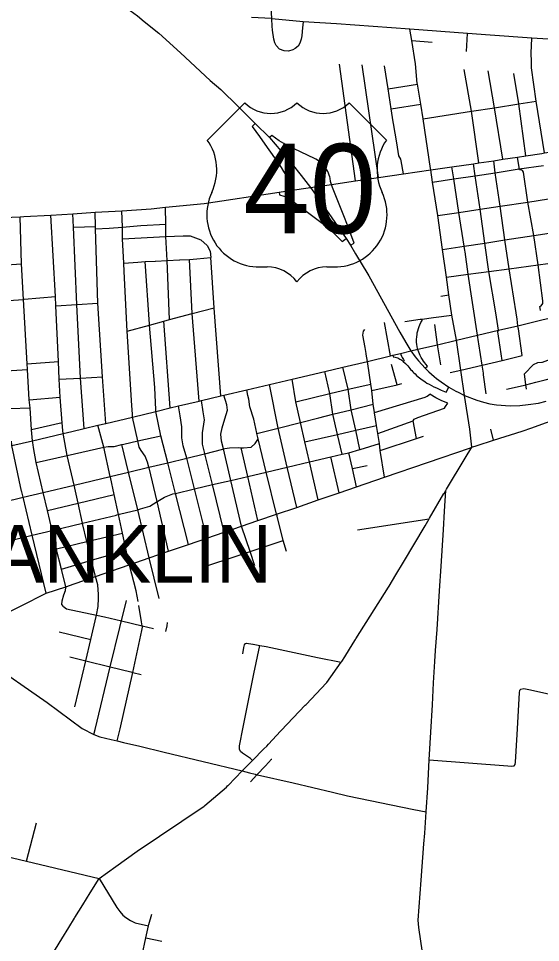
# Model space of a CAD drawing. Extents: x 1755200 to 1902939, y 644115 to 788070.
# Drawn here: x 1811230 to 1819343, y 701476 to 715838 of the extents above; entities that cross this region are included whole.
import ezdxf

# ---------------------------------------------------------------- set-up
doc = ezdxf.new("R2010")
doc.units = 0
for name, color, linetype in [('GM_X_City_Street', 7, 'Continuous'), ('GM_X_County_Road', 7, 'Continuous'), ('GM_X_Interchange_Ramps', 7, 'Continuous'), ('GM_X_Interstate_Route', 7, 'Continuous'), ('GM_X_Township_Road', 7, 'Continuous'), ('GM_X_Township_Text', 7, 'Continuous'), ('GM_X_US_Route', 7, 'Continuous'), ('GM_X_US_Shield', 7, 'Continuous')]:
    doc.layers.add(name, color=color, linetype=linetype)

msp = doc.modelspace()

# ---------------------------------------------------------------- linework, layer by layer
at = {"layer": 'GM_X_City_Street'}
for points in [[(1815173, 715717), (1815167, 715834), (1815156, 716028), (1815156, 716120), (1815160, 716213), (1815173, 716390), (1815193, 716667), (1815266, 717013)], [(1815164, 715835), (1814849, 715853)], [(1817314, 715673), (1816174, 715756), (1815653, 715786), (1815167, 715834), (1815164, 715835)], [(1815632, 715569), (1815621, 715518), (1815602, 715455), (1815574, 715407), (1815531, 715370), (1815495, 715351), (1815424, 715332), (1815357, 715336), (1815288, 715363), (1815236, 715416), (1815215, 715459), (1815198, 715518), (1815177, 715654), (1815173, 715717)], [(1815653, 715786), (1815643, 715691), (1815633, 715574), (1815632, 715569)], [(1819634, 715506), (1819210, 715534), (1818559, 715578), (1818207, 715605), (1817314, 715673)], [(1817633, 713505), (1817517, 714278), (1817480, 714507), (1817430, 714816), (1817428, 714828), (1817400, 715133), (1817342, 715495), (1817314, 715673)], [(1818194, 715322), (1818207, 715605)], [(1819201, 715171), (1819198, 715300), (1819210, 715534)], [(1817342, 715495), (1817659, 715470)], [(1816466, 713313), (1816217, 715127)], [(1816823, 713365), (1816573, 715119)], [(1817054, 714231), (1817022, 714433), (1816973, 714743), (1816916, 715100)], [(1819403, 713749), (1819276, 714553), (1819204, 715069), (1819201, 715171)], [(1818382, 713593), (1818269, 714396), (1818157, 715046)], [(1818756, 713649), (1818628, 714451), (1818530, 715024)], [(1819116, 713703), (1819003, 714510), (1818926, 714985)], [(1816973, 714743), (1817430, 714816)], [(1817517, 714278), (1818269, 714396), (1818628, 714451), (1819003, 714510), (1819276, 714553)], [(1817022, 714433), (1817480, 714507)], [(1817175, 713626), (1817170, 713652), (1817139, 713701), (1817108, 713905), (1817058, 714207), (1817054, 714231)], [(1819009, 713521), (1818984, 713684)], [(1817211, 713422), (1817176, 713623), (1817175, 713626)], [(1818169, 712211), (1818166, 712232), (1818156, 712299), (1818072, 712824), (1817995, 713343), (1817965, 713531)], [(1817995, 713343), (1818327, 713393), (1818640, 713441), (1819012, 713500), (1819390, 713554)], [(1818748, 710520), (1818701, 710832), (1818679, 710967), (1818688, 710994), (1818646, 711261), (1818537, 711906), (1818478, 712348), (1818404, 712874), (1818327, 713393), (1818303, 713580)], [(1818978, 711164), (1818964, 711261), (1818854, 711948), (1818788, 712395), (1818717, 712921), (1818640, 713441), (1818617, 713626)], [(1819343, 711297), (1819342, 711302), (1819333, 711362), (1819353, 711372), (1819376, 711409), (1819376, 711450), (1819304, 712008), (1819237, 712464), (1819143, 712985), (1819076, 713449), (1819063, 713477), (1819041, 713487), (1819014, 713487), (1819012, 713500), (1819009, 713521)], [(1817819, 712248), (1817745, 712775), (1817666, 713295), (1817636, 713485), (1817633, 713505)], [(1817666, 713295), (1817995, 713343)], [(1817745, 712775), (1818072, 712824), (1818404, 712874), (1818717, 712921), (1819143, 712985), (1819468, 713033), (1819623, 713055)], [(1812253, 709466), (1812195, 710249), (1812139, 711391), (1812086, 712592), (1812076, 712803)], [(1812589, 709545), (1812534, 710266), (1812465, 711412), (1812427, 712570), (1812425, 712607), (1812422, 712827)], [(1813001, 709686), (1812990, 709821), (1812919, 710977), (1812872, 711906), (1812865, 712034), (1812846, 712414), (1812846, 712596), (1812835, 712849)], [(1813578, 711158), (1813538, 712077), (1813522, 712447), (1813522, 712643), (1813516, 712905)], [(1811465, 709169), (1811457, 709212), (1811446, 709272), (1811432, 709443), (1811413, 709787), (1811395, 709908), (1811369, 710384), (1811369, 710388), (1811364, 710470), (1811309, 711472), (1811279, 712024), (1811256, 712755)], [(1811918, 709434), (1811908, 709555), (1811878, 709951), (1811862, 710233), (1811850, 710504), (1811812, 711369), (1811805, 711515), (1811735, 712781)], [(1812086, 712592), (1812425, 712607)], [(1812427, 712570), (1812641, 712579), (1812846, 712596)], [(1812846, 712596), (1813132, 712618), (1813522, 712643)], [(1812846, 712414), (1813522, 712447), (1813788, 712459), (1813867, 712457)], [(1813867, 712457), (1813869, 712457), (1813896, 712457), (1814061, 712399), (1814161, 712310), (1814209, 712220), (1814219, 712122)], [(1813358, 712068), (1813538, 712077), (1813733, 712087), (1813735, 712087)], [(1813735, 712087), (1813885, 712094), (1814004, 712104), (1814004, 712104)], [(1814038, 709890), (1813929, 711251), (1813885, 712094)], [(1814004, 712104), (1814219, 712122)], [(1814270, 711335), (1814269, 711340), (1814219, 712122)], [(1818383, 710781), (1818378, 710811), (1818361, 710916), (1818220, 711864), (1818169, 712211)], [(1810647, 711977), (1810973, 712002), (1811279, 712024)], [(1812865, 712034), (1813082, 712052), (1813086, 712052)], [(1813086, 712052), (1813196, 712061), (1813354, 712068), (1813358, 712068)], [(1813267, 711087), (1813196, 712061)], [(1817879, 711819), (1818220, 711864), (1818537, 711906), (1818854, 711948), (1819304, 712008), (1819608, 712048), (1819763, 712068)], [(1810682, 711426), (1810995, 711449), (1811309, 711472), (1811317, 711473), (1811805, 711515)], [(1817794, 711523), (1817917, 711542)], [(1811812, 711369), (1812139, 711391), (1812465, 711412)], [(1812919, 710977), (1813268, 711071), (1813491, 711131), (1813578, 711158), (1813929, 711251), (1814269, 711340)], [(1814374, 709971), (1814270, 711334), (1814270, 711335)], [(1817235, 711129), (1817470, 711162), (1817504, 711166), (1817680, 711191), (1817962, 711224)], [(1818037, 710839), (1818361, 710916), (1818688, 710994), (1818992, 711063), (1819364, 711153), (1819710, 711233), (1819868, 711271), (1820152, 711337)], [(1813364, 709756), (1813347, 710101), (1813268, 711071), (1813268, 711073), (1813267, 711084), (1813267, 711087)], [(1813588, 709784), (1813491, 711131)], [(1817010, 710596), (1816918, 711113)], [(1817739, 710767), (1817698, 711081)], [(1819000, 711012), (1818997, 711028), (1818992, 711063), (1818978, 711164)], [(1816632, 710631), (1816618, 710722), (1816581, 710916), (1816590, 710976), (1816614, 711006)], [(1819056, 710601), (1819000, 711012)], [(1811127, 709200), (1811446, 709272), (1811922, 709387), (1812059, 709420), (1812253, 709466), (1812465, 709515), (1812589, 709545), (1813004, 709643), (1813365, 709730), (1813588, 709784), (1813719, 709816), (1814038, 709890), (1814074, 709898), (1814374, 709971), (1814422, 709982), (1814779, 710066), (1815131, 710149), (1815483, 710232), (1815989, 710351), (1816269, 710420), (1816652, 710508), (1817010, 710596), (1817048, 710605), (1817167, 710633), (1817329, 710673), (1817435, 710700), (1817739, 710767), (1818037, 710839)], [(1818458, 710301), (1818455, 710326), (1818437, 710451), (1818383, 710781)], [(1817791, 710454), (1817739, 710767)], [(1819270, 710185), (1819415, 710223), (1819688, 710296), (1819991, 710376), (1819999, 710377), (1820295, 710439), (1820612, 710506), (1820953, 710578), (1821276, 710647), (1821610, 710723), (1821757, 710761)], [(1811364, 710470), (1811850, 710504)], [(1816918, 708708), (1816852, 709123), (1816838, 709233), (1816813, 709385), (1816793, 709511), (1816761, 709708), (1816761, 709712), (1816741, 709842), (1816721, 710055), (1816707, 710155), (1816686, 710292), (1816652, 710508), (1816634, 710620), (1816632, 710631)], [(1817937, 710337), (1818104, 710374), (1818437, 710451), (1818590, 710485), (1818748, 710520), (1819056, 710601)], [(1819092, 710317), (1819235, 710462), (1819301, 710490), (1819365, 710498), (1819371, 710498), (1819630, 710593), (1819641, 710596), (1819767, 710624)], [(1810389, 710321), (1810737, 710343), (1811039, 710362), (1811369, 710384)], [(1816262, 709064), (1816189, 709373), (1816115, 709686), (1816067, 710008), (1815989, 710351)], [(1816537, 709139), (1816471, 709437), (1816401, 709757), (1816352, 710074), (1816269, 710420)], [(1817116, 710146), (1817029, 710461)], [(1811862, 710233), (1812195, 710249), (1812534, 710266)], [(1815886, 708354), (1815750, 708945), (1815678, 709257), (1815610, 709558), (1815538, 709881), (1815483, 710232)], [(1818499, 710002), (1818458, 710301)], [(1819125, 710074), (1819116, 710143), (1819092, 710317)], [(1815249, 708103), (1815249, 708105), (1815242, 708133), (1815081, 708788), (1814956, 709303), (1814936, 709385), (1814934, 709392), (1814886, 709610), (1814824, 709804), (1814809, 709920), (1814795, 709979), (1814779, 710066)], [(1815553, 708239), (1815406, 708865), (1815263, 709469), (1815131, 710149)], [(1815538, 709881), (1816067, 710008), (1816352, 710074), (1816707, 710155)], [(1816721, 710055), (1817116, 710146), (1817185, 710162)], [(1818815, 710075), (1819074, 710133), (1819094, 710138), (1819116, 710143), (1819270, 710185)], [(1811395, 709908), (1811878, 709951)], [(1814700, 707931), (1814695, 707945), (1814529, 708658), (1814415, 709147), (1814386, 709267), (1814373, 709375), (1814393, 709477), (1814434, 709613), (1814476, 709748), (1814468, 709833), (1814422, 709982)], [(1816761, 709712), (1817552, 709950), (1817583, 709965), (1817625, 710000)], [(1817901, 709859), (1817808, 709896), (1817715, 709939), (1817625, 710000)], [(1810424, 709718), (1810770, 709745), (1811095, 709774), (1811413, 709787)], [(1814159, 707761), (1813965, 708526), (1813844, 709002), (1813789, 709197), (1813769, 709318), (1813768, 709493), (1813744, 709660), (1813719, 709816)], [(1814428, 707853), (1814245, 708592), (1814126, 709070), (1814125, 709077), (1814088, 709224), (1814088, 709298), (1814092, 709398), (1814110, 709530), (1814119, 709598), (1814111, 709663), (1814100, 709725), (1814074, 709898)], [(1814936, 709385), (1815263, 709469), (1815610, 709558), (1815897, 709631), (1816115, 709686), (1816401, 709757), (1816741, 709842)], [(1816813, 709385), (1817364, 709584), (1817380, 709609), (1817436, 709636), (1817850, 709782), (1817868, 709807), (1817901, 709859)], [(1813563, 707557), (1813383, 708329), (1813261, 708853), (1813258, 708863), (1813235, 708944), (1813197, 709033), (1813137, 709123), (1813104, 709176), (1813085, 709271), (1813084, 709275), (1813004, 709643), (1813001, 709686)], [(1813874, 707663), (1813672, 708457), (1813551, 708933), (1813444, 709353), (1813365, 709730), (1813364, 709756)], [(1811908, 709555), (1811432, 709443)], [(1812952, 707347), (1812904, 707572), (1812847, 707839), (1812784, 708128), (1812718, 708438), (1812659, 708709), (1812657, 708720), (1812554, 709175), (1812465, 709515)], [(1815678, 709257), (1816189, 709373), (1816471, 709437), (1816793, 709511)], [(1817415, 709308), (1817364, 709584)], [(1818360, 709201), (1818612, 709282), (1819059, 709426), (1819208, 709477), (1819422, 709552), (1819508, 709582), (1819562, 709600)], [(1811507, 708936), (1811987, 709046), (1812554, 709175), (1812625, 709186), (1812715, 709187), (1812837, 709215), (1812869, 709222), (1813085, 709271), (1813444, 709353)], [(1812422, 707187), (1812366, 707416), (1812294, 707707), (1812225, 707989), (1812224, 707993), (1812155, 708304), (1812093, 708585), (1811987, 709046), (1811931, 709362), (1811922, 709387), (1811918, 709434)], [(1816852, 709123), (1817415, 709308), (1817526, 709345)], [(1818612, 709282), (1818569, 709455)], [(1811277, 708492), (1811127, 709200), (1811123, 709267)], [(1813417, 706822), (1813263, 707454), (1813082, 708203), (1812940, 708787), (1812837, 709215)], [(1812952, 707347), (1813263, 707454), (1813563, 707557), (1813874, 707663), (1814159, 707761), (1814428, 707853), (1814695, 707945), (1814952, 708033), (1815242, 708133), (1815553, 708239), (1815886, 708354), (1816215, 708467), (1816485, 708559), (1816918, 708708), (1818255, 709167), (1818275, 709174), (1818360, 709201)], [(1814436, 709152), (1814437, 709152), (1814508, 709167), (1814648, 709168), (1814691, 709165), (1814728, 709162), (1814845, 709175), (1814910, 709230), (1814938, 709279), (1814956, 709303)], [(1816538, 709139), (1816838, 709233)], [(1809639, 708001), (1810005, 708088), (1810353, 708171), (1810659, 708244), (1810988, 708322), (1811300, 708397), (1811615, 708472), (1812093, 708585), (1812657, 708720), (1812940, 708787), (1813258, 708863), (1813551, 708933), (1813844, 709002), (1814122, 709069), (1814126, 709070), (1814407, 709146), (1814415, 709147), (1814436, 709152)], [(1811889, 707308), (1811886, 707319), (1811833, 707540), (1811820, 707593), (1811753, 707880), (1811681, 708191), (1811615, 708472), (1811507, 708936), (1811465, 709169)], [(1812752, 708120), (1812754, 708121), (1812784, 708128), (1812800, 708132), (1813082, 708203), (1813125, 708214), (1813272, 708259), (1813383, 708329), (1813397, 708338), (1813500, 708400), (1813630, 708447), (1813672, 708457), (1813965, 708526), (1814245, 708592), (1814455, 708641), (1814529, 708658), (1814793, 708721), (1815081, 708788), (1815406, 708865), (1815750, 708945), (1816086, 709025), (1816262, 709064), (1816365, 709088), (1816537, 709139), (1816538, 709139)], [(1814952, 708033), (1814793, 708721), (1814691, 709165)], [(1816485, 708559), (1816421, 708841), (1816365, 709088)], [(1816215, 708467), (1816086, 709025)], [(1816421, 708841), (1816647, 708890)], [(1811659, 706904), (1811442, 707805), (1811300, 708397), (1811280, 708480), (1811277, 708492)], [(1817851, 708181), (1817869, 708501)], [(1811681, 708191), (1812155, 708304), (1812718, 708438)], [(1810815, 707653), (1810815, 707653), (1811125, 707728), (1811442, 707805), (1811753, 707880), (1812224, 707993), (1812752, 708120)], [(1815395, 707553), (1815343, 707722), (1815249, 708103)], [(1814905, 707332), (1814830, 707552), (1814700, 707930), (1814700, 707931)], [(1811820, 707593), (1812294, 707707), (1812847, 707839)], [(1814611, 707480), (1814611, 707480), (1814830, 707552), (1815343, 707722)], [(1811896, 707279), (1812366, 707416), (1812904, 707572)], [(1814124, 707319), (1814611, 707480)], [(1807606, 707144), (1807927, 707100), (1807937, 707099), (1808229, 707057), (1808515, 707017), (1808525, 707015), (1808870, 706939), (1809249, 706853), (1809618, 706775), (1809997, 706692), (1810006, 706690), (1810372, 706605), (1810720, 706524), (1810820, 706507), (1810850, 706503), (1810880, 706511), (1811659, 706904), (1811963, 707006), (1812095, 707050), (1812428, 707165), (1812952, 707347)], [(1813092, 706774), (1813060, 706942), (1812954, 707342), (1812952, 707347)], [(1811930, 706699), (1811903, 706731), (1811907, 706787), (1811933, 706879), (1811959, 706945), (1811966, 706993), (1811963, 707006), (1811896, 707279), (1811889, 707308)], [(1812472, 706826), (1812472, 706831), (1812475, 706884), (1812462, 707033), (1812428, 707165), (1812422, 707187)], [(1812105, 705139), (1812275, 705853), (1812354, 706187), (1812438, 706542), (1812442, 706563), (1812466, 706699), (1812472, 706826)], [(1812805, 706370), (1812827, 706460), (1812830, 706474), (1812908, 706791)], [(1811930, 706699), (1811975, 706662), (1812442, 706563), (1812564, 706537), (1812830, 706474), (1813154, 706397), (1813328, 706356)], [(1812761, 704608), (1812811, 704798), (1813005, 705673), (1813149, 706323), (1813158, 706379), (1813154, 706397), (1813140, 706460), (1813098, 706715)], [(1812401, 704708), (1812420, 704788), (1812657, 705759), (1812805, 706370)], [(1813518, 706311), (1813541, 706398), (1813548, 706449)], [(1811863, 706305), (1812354, 706187)], [(1810583, 705964), (1810591, 705959), (1810735, 705861), (1811674, 705206), (1812217, 704801), (1812401, 704708), (1812492, 704675), (1812669, 704629), (1812761, 704608), (1812860, 704585)], [(1812026, 705915), (1812275, 705853), (1812657, 705759), (1812976, 705681)], [(1812976, 705681), (1812976, 705681), (1813005, 705673), (1813134, 705642)], [(1812860, 704585), (1813118, 704525), (1813496, 704435), (1814706, 704145)], [(1804587, 704387), (1804884, 704291), (1805626, 704054), (1806239, 703914), (1806558, 703842), (1806871, 703772), (1807204, 703697), (1807447, 703642), (1807701, 703584), (1807975, 703522), (1808509, 703402), (1809302, 703223), (1809996, 703066), (1810269, 703001), (1810590, 702923), (1811352, 702740), (1811574, 702687), (1812483, 702469)], [(1814834, 703972), (1814936, 704083), (1815066, 704222), (1815164, 704327), (1815165, 704328)], [(1814706, 704145), (1814820, 704114), (1814908, 704090)], [(1811352, 702740), (1811508, 703338)], [(1812483, 702469), (1812756, 702022), (1812804, 701958), (1812853, 701903), (1812896, 701866), (1812969, 701816), (1813044, 701781), (1813249, 701734)], [(1813255, 701754), (1813255, 701755), (1813300, 701915)], [(1813070, 700880), (1813154, 701278), (1813210, 701548), (1813249, 701734), (1813255, 701754)], [(1813210, 701548), (1813458, 701496)]]:
    msp.add_lwpolyline(points, dxfattribs=at)
at = {"layer": 'GM_X_County_Road'}
for points in [[(1817533, 701143), (1817450, 701707), (1817443, 701825), (1817489, 702443), (1817530, 703011), (1817543, 703177), (1817566, 703505), (1817591, 703881), (1817611, 704316), (1817637, 704743), (1817662, 705171), (1817682, 705514), (1817701, 705841), (1817711, 706013), (1817734, 706340), (1817775, 706942), (1817801, 707326), (1817835, 707892), (1817851, 708181)], [(1817611, 704316), (1818834, 704221), (1818895, 704215), (1818932, 704220), (1818946, 704242), (1818954, 704280), (1818979, 704707), (1819015, 705356), (1819023, 705398), (1819037, 705412), (1819083, 705422), (1819185, 705402), (1819948, 705233)]]:
    msp.add_lwpolyline(points, dxfattribs=at)
at = {"layer": 'GM_X_Interchange_Ramps'}
for points in [[(1814906, 714207), (1814863, 714158), (1814977, 714002), (1815095, 713835), (1815259, 713601), (1815313, 713520), (1815350, 713460), (1815369, 713429), (1815382, 713402), (1815394, 713372), (1815402, 713347), (1815409, 713321), (1815415, 713293), (1815419, 713256), (1815423, 713231), (1815435, 713201), (1815449, 713162)], [(1816095, 713258), (1816079, 713305), (1816071, 713356), (1816066, 713377), (1816058, 713405), (1816048, 713431), (1816036, 713457), (1816021, 713486), (1816005, 713512), (1815984, 713539), (1815964, 713562), (1815942, 713585), (1815914, 713609), (1815879, 713634), (1815851, 713650), (1815832, 713660), (1815513, 713811), (1815472, 713829), (1815429, 713850), (1815391, 713870), (1815352, 713893), (1815319, 713913), (1815281, 713938), (1815169, 714017), (1815133, 713987)], [(1816388, 712313), (1816444, 712346), (1816409, 712443), (1816383, 712510), (1816359, 712577), (1816342, 712626), (1816285, 712770), (1816112, 713213), (1816095, 713258)], [(1815281, 713137), (1815287, 713096), (1815356, 713076), (1815386, 713064), (1815412, 713052), (1815442, 713035), (1815468, 713016), (1815497, 712993), (1815868, 712716), (1815969, 712640), (1816055, 712572), (1816085, 712543), (1816108, 712521), (1816130, 712500), (1816156, 712475), (1816181, 712450), (1816203, 712428), (1816224, 712407), (1816258, 712372), (1816322, 712420)], [(1815449, 713162), (1815456, 713115), (1815462, 713092), (1815471, 713068), (1815482, 713047), (1815492, 713031), (1815510, 713010), (1815497, 712993)], [(1817551, 710401), (1817586, 710432), (1817561, 710464), (1817543, 710486), (1817524, 710511), (1817508, 710535), (1817488, 710569), (1817473, 710597), (1817460, 710626), (1817450, 710651), (1817441, 710678), (1817435, 710700), (1817433, 710706), (1817426, 710738), (1817421, 710773), (1817417, 710809), (1817416, 710848), (1817418, 710890), (1817423, 710928), (1817427, 710951), (1817434, 710984), (1817444, 711018), (1817455, 711051), (1817467, 711078), (1817483, 711110), (1817494, 711130), (1817501, 711142), (1817504, 711166)], [(1817048, 710605), (1817052, 710579), (1817086, 710573), (1817102, 710569), (1817123, 710561), (1817142, 710553), (1817156, 710545), (1817171, 710536), (1817186, 710525), (1817210, 710505), (1817244, 710477), (1817261, 710460), (1817272, 710448), (1817279, 710438), (1817295, 710418), (1817310, 710400), (1817324, 710384), (1817341, 710365), (1817356, 710348), (1817373, 710332), (1817392, 710313), (1817417, 710290), (1817439, 710270), (1817460, 710253), (1817480, 710237), (1817504, 710220), (1817527, 710204), (1817551, 710188), (1817578, 710171), (1817612, 710152), (1817647, 710133), (1817684, 710115), (1817726, 710097), (1817799, 710063), (1817877, 710031), (1817920, 710107)], [(1817167, 710633), (1817171, 710613), (1817182, 710590), (1817195, 710567), (1817204, 710551), (1817214, 710535), (1817226, 710515), (1817210, 710505)]]:
    msp.add_lwpolyline(points, dxfattribs=at)
at = {"layer": 'GM_X_Interstate_Route'}
for points in [[(1812533, 716247), (1812678, 716161), (1812775, 716100), (1812908, 716002), (1813077, 715880), (1813183, 715790), (1813411, 715611), (1813749, 715304), (1814209, 714873), (1814376, 714732), (1814645, 714472), (1814906, 714207), (1815133, 713987), (1815483, 713571), (1815623, 713399), (1815769, 713210)], [(1815769, 713210), (1815857, 713086)], [(1815857, 713086), (1815971, 712926), (1816322, 712420), (1816388, 712313), (1816469, 712178)], [(1816469, 712178), (1816660, 711864)], [(1816660, 711864), (1816675, 711839), (1817158, 710962), (1817251, 710800), (1817329, 710673)], [(1817329, 710673), (1817397, 710581), (1817448, 710516), (1817551, 710401)], [(1817551, 710401), (1817609, 710344), (1817689, 710273), (1817728, 710241), (1817799, 710189), (1817920, 710107), (1818025, 710047), (1818064, 710028)], [(1818064, 710028), (1818162, 709980), (1818354, 709903), (1818455, 709874), (1818556, 709850), (1818660, 709834), (1818871, 709818), (1819020, 709821), (1819151, 709837), (1819311, 709860), (1819429, 709891)]]:
    msp.add_lwpolyline(points, dxfattribs=at)
at = {"layer": 'GM_X_Township_Road'}
for points in [[(1816497, 707890), (1817613, 708061)], [(1814864, 704304), (1814834, 704335), (1814710, 704419), (1814680, 704444), (1814663, 704480), (1814664, 704535), (1814721, 704822), (1814888, 705652), (1814983, 706093)], [(1814716, 705961), (1814731, 706059), (1814741, 706105), (1814758, 706125), (1814774, 706131), (1814874, 706112)], [(1814874, 706112), (1814877, 706112), (1814983, 706093), (1815077, 706075), (1815878, 705908), (1816246, 705832)], [(1814908, 704090), (1814936, 704083), (1814945, 704080), (1815500, 703957), (1816111, 703813), (1816342, 703758), (1817376, 703545), (1817566, 703505)]]:
    msp.add_lwpolyline(points, dxfattribs=at)
at = {"layer": 'GM_X_US_Route'}
for points in [[(1816095, 713258), (1816466, 713313), (1816823, 713365), (1817211, 713422), (1817636, 713485), (1817965, 713531), (1818303, 713580), (1818382, 713593), (1818617, 713626), (1818756, 713649), (1818984, 713684), (1819116, 713703), (1819365, 713741), (1819403, 713749), (1819805, 713806), (1820123, 713854), (1820280, 713876)], [(1815769, 713210), (1816095, 713258)], [(1811311, 712758), (1811735, 712781), (1812076, 712803), (1812422, 712827), (1812835, 712849), (1813292, 712880), (1813516, 712905), (1814114, 712964), (1815281, 713137)], [(1815281, 713137), (1815281, 713137), (1815449, 713162), (1815769, 713210)], [(1807602, 712555), (1807934, 712562), (1808231, 712580), (1808266, 712582), (1808530, 712604), (1808612, 712609), (1808913, 712626), (1808960, 712629), (1809119, 712631), (1809250, 712639), (1809333, 712644), (1809624, 712668), (1809728, 712670), (1809970, 712683), (1810073, 712689), (1810276, 712704), (1810424, 712716), (1810631, 712720), (1810706, 712721), (1810942, 712741), (1810997, 712744), (1811256, 712755), (1811311, 712758)], [(1817819, 712248), (1818156, 712299), (1818478, 712348), (1818788, 712395), (1819237, 712464), (1819542, 712510), (1819973, 712575)], [(1818162, 709980), (1818104, 710374), (1818037, 710839), (1817962, 711224), (1817917, 711542), (1817879, 711819), (1817819, 712248)], [(1818275, 709174), (1818245, 709454), (1818162, 709980)], [(1818174, 709005), (1818275, 709174)], [(1817843, 708455), (1817869, 708501), (1817881, 708521), (1818173, 709005), (1818174, 709005)], [(1815116, 704560), (1815303, 704762), (1815311, 704771), (1815687, 705163), (1815699, 705175), (1816014, 705510), (1816020, 705515), (1816246, 705832), (1816253, 705842), (1816299, 705917), (1816431, 706128), (1816467, 706185), (1816473, 706194), (1816980, 706997), (1816989, 707012), (1817095, 707189), (1817211, 707385), (1817548, 707952), (1817613, 708061), (1817619, 708072), (1817842, 708455), (1817843, 708455)], [(1814706, 704145), (1814864, 704304), (1815043, 704484)], [(1815043, 704484), (1815087, 704528), (1815116, 704560)], [(1814482, 703914), (1814486, 703918), (1814706, 704145)], [(1812744, 702658), (1813075, 702896), (1814114, 703595), (1814126, 703603), (1814460, 703892), (1814482, 703914)], [(1812346, 702250), (1812483, 702469), (1812742, 702656), (1812744, 702658)], [(1812102, 701855), (1812108, 701866), (1812230, 702063), (1812346, 702250)], [(1811362, 700675), (1811384, 700709), (1811562, 700989), (1811803, 701374), (1811901, 701532), (1812011, 701708), (1812102, 701855)]]:
    msp.add_lwpolyline(points, dxfattribs=at)
at = {"layer": 'GM_X_US_Shield'}
for p, q in [((1814745, 714528), (1814165, 713948)), ((1816949, 713948), (1816369, 714528)), ((1814977, 711976), (1815093, 711976)), ((1816021, 711976), (1816137, 711976))]:
    msp.add_line(p, q, dxfattribs=at)
for centre, radius, start, end in [((1815151, 714943), 580, 225.573, 314.427), ((1815963, 714943), 580, 225.573, 314.427), ((1813499, 713483), 812, 334.5471, 35.0009), ((1817614, 713483), 812, 144.9991, 205.4529), ((1814968, 712788), 812, 154.8319, 270.6383), ((1816146, 712788), 812, 269.3617, 25.1681), ((1815093, 711396), 580, 36.8699, 90), ((1816021, 711396), 580, 90, 143.1301)]:
    msp.add_arc(centre, radius, start, end, dxfattribs=at)

# ---------------------------------------------------------------- texts
at = {"layer": 'GM_X_Township_Text'}
msp.add_text('FRANKLIN', height=900, rotation=0, dxfattribs=at).set_placement((1809216, 707067))
at = {"layer": 'GM_X_US_Shield'}
msp.add_text('40', height=1392.2, dxfattribs=at).set_placement((1814721, 712498))

doc.saveas('drawing.dxf')
